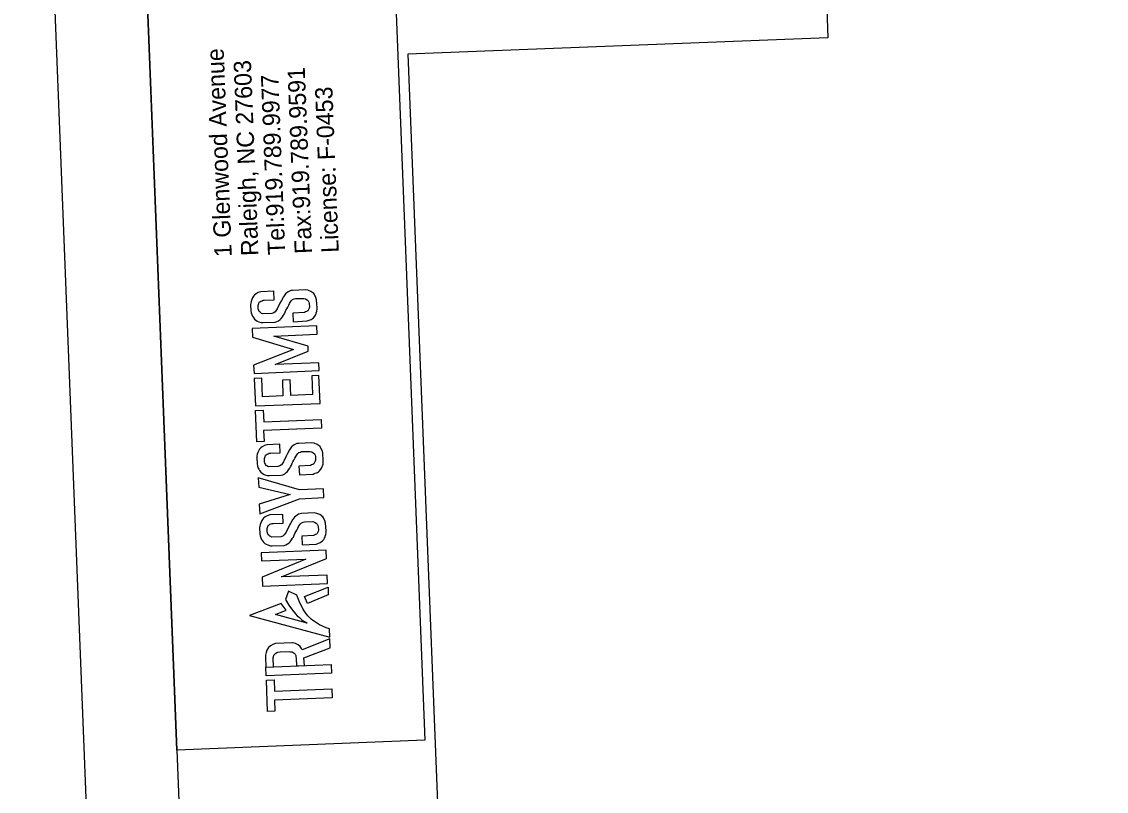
# Model space of a CAD drawing. Extents: x 1627804 to 1628970, y 763730 to 765944.
# Drawn here: x 1627803.6 to 1628095.2, y 765265.9 to 765472.6 of the extents above; entities that cross this region are included whole.
import ezdxf

# ---------------------------------------------------------------- set-up
doc = ezdxf.new("R2010")
doc.units = 0
for name, color, linetype in [('Exist Right of Way Monument Leader', 7, 'Continuous'), ('Exist Right of Way Monument Text', 7, 'Continuous'), ('Exist Roads EOT', 7, 'Continuous'), ('Exist Structure Major Deck Tunnel Box Culvert', 7, 'Continuous'), ('Exist Utilities Gas UG Line', 7, 'Continuous'), ('Scratch_Level_1', 7, 'Continuous')]:
    doc.layers.add(name, color=color, linetype=linetype)

msp = doc.modelspace()

# ---------------------------------------------------------------- linework, layer by layer
at = {"layer": 'Exist Right of Way Monument Leader'}
msp.add_lwpolyline([(1627845.35, 765276.95), (1627837.47, 765476.85), (1627904.11, 765479.48), (1627911.99, 765279.58)], close=True, dxfattribs=at)
at = {"layer": 'Exist Right of Way Monument Text'}
msp.add_lwpolyline([(1627829.58, 765676.74), (1627888.69, 764177.91), (1628937.87, 764219.28), (1628878.77, 765718.12)], close=True, dxfattribs=at)
at = {"layer": 'Exist Roads EOT'}
for points in [[(1627871.45, 765397.9), (1627871.36, 765400.21), (1627867.88, 765400.07), (1627867.19, 765399.84), (1627866.61, 765399.54), (1627866.23, 765399.23), (1627865.89, 765398.84), (1627865.63, 765398.39), (1627865.47, 765397.96), (1627865.47, 765397.96), (1627865.29, 765397.49), (1627865.19, 765397.01), (1627865.12, 765396.68), (1627865.23, 765394.94), (1627865.34, 765394.41), (1627865.44, 765393.96), (1627865.7, 765393.51), (1627865.92, 765393.11), (1627866.22, 765392.73), (1627866.55, 765392.43), (1627866.92, 765392.2), (1627867.32, 765392.02), (1627868.03, 765391.8), (1627868.55, 765391.77), (1627871.71, 765391.89), (1627872.18, 765392.03), (1627872.67, 765392.27), (1627873.07, 765392.58), (1627873.37, 765392.89), (1627873.7, 765393.35), (1627874.03, 765393.82), (1627874.23, 765394.11), (1627874.44, 765394.6), (1627874.65, 765395.09), (1627874.88, 765395.49), (1627875.15, 765395.95), (1627875.4, 765396.48), (1627875.6, 765396.93), (1627875.9, 765397.37), (1627876.18, 765397.69), (1627876.41, 765397.95), (1627876.88, 765398.12), (1627877.18, 765398.23), (1627879.41, 765398.28), (1627879.9, 765398.14), (1627880.33, 765397.91), (1627880.64, 765397.59), (1627880.81, 765397.24), (1627880.9, 765396.91), (1627880.95, 765395.95), (1627880.88, 765395.62), (1627880.7, 765395.28), (1627880.52, 765394.95), (1627880.19, 765394.79), (1627879.86, 765394.64), (1627879.6, 765394.51), (1627876.49, 765394.35), (1627876.61, 765392.02), (1627880.31, 765392.21), (1627880.59, 765392.34), (1627881.44, 765392.64), (1627881.73, 765392.83), (1627882.03, 765393.09), (1627882.39, 765393.49), (1627882.57, 765393.8), (1627882.74, 765394.24), (1627882.8, 765394.4), (1627882.96, 765394.84), (1627883, 765395.38), (1627883.02, 765395.77), (1627882.88, 765397.91), (1627882.72, 765398.5), (1627882.31, 765399.31), (1627882.17, 765399.58), (1627881.36, 765400.17), (1627880.56, 765400.47), (1627879.84, 765400.6), (1627876.43, 765400.41), (1627875.95, 765400.39), (1627875.58, 765400.24), (1627875.24, 765400.03), (1627874.5, 765399.47), (1627873.97, 765398.74), (1627873.43, 765397.74), (1627873.02, 765396.98), (1627872.31, 765395.49), (1627871.78, 765394.71), (1627871.37, 765394.37), (1627871.09, 765394.28), (1627870.81, 765394.19), (1627868.38, 765394.14), (1627868.12, 765394.25), (1627867.86, 765394.37), (1627867.7, 765394.54), (1627867.49, 765394.76), (1627867.38, 765395.02), (1627867.26, 765395.27), (1627867.28, 765395.42), (1627867.21, 765395.43), (1627867.18, 765396.39), (1627867.28, 765396.67), (1627867.38, 765396.95), (1627867.48, 765397.23), (1627867.67, 765397.37), (1627867.94, 765397.57), (1627868.21, 765397.67), (1627868.48, 765397.77), (1627868.79, 765397.78)], [(1627876.67, 765384.57), (1627865.91, 765380.33), (1627866.1, 765378.12), (1627883.55, 765378.9), (1627883.45, 765381), (1627871.78, 765380.48), (1627880.64, 765384.1), (1627880.62, 765385.45), (1627871.37, 765388.16), (1627883.08, 765388.66), (1627882.98, 765390.94), (1627865.58, 765390.19), (1627865.68, 765387.89)], [(1627866.12, 765376.77), (1627866.42, 765369.39), (1627883.83, 765370.09), (1627883.53, 765377.56), (1627881.56, 765377.48), (1627881.76, 765372.44), (1627875.93, 765372.2), (1627875.76, 765376.41), (1627873.68, 765376.33), (1627873.85, 765372.08), (1627868.36, 765371.86), (1627868.16, 765376.87)], [(1627866.8, 765359.71), (1627866.46, 765368.17), (1627868.53, 765368.25), (1627868.66, 765365.15), (1627884.07, 765365.77), (1627884.16, 765363.42), (1627868.65, 765362.79), (1627868.77, 765359.82)], [(1627873.11, 765356.8), (1627873.02, 765359.11), (1627869.54, 765358.97), (1627868.84, 765358.74), (1627868.27, 765358.44), (1627867.89, 765358.13), (1627867.55, 765357.74), (1627867.29, 765357.29), (1627867.13, 765356.86), (1627867.13, 765356.86), (1627866.95, 765356.4), (1627866.85, 765355.91), (1627866.78, 765355.58), (1627866.89, 765353.84), (1627867, 765353.31), (1627867.1, 765352.86), (1627867.35, 765352.41), (1627867.58, 765352.01), (1627867.88, 765351.63), (1627868.21, 765351.33), (1627868.58, 765351.1), (1627868.98, 765350.93), (1627869.69, 765350.7), (1627870.21, 765350.67), (1627873.37, 765350.79), (1627873.84, 765350.93), (1627874.33, 765351.18), (1627874.73, 765351.48), (1627875.03, 765351.79), (1627875.36, 765352.25), (1627875.69, 765352.72), (1627875.89, 765353.01), (1627876.1, 765353.5), (1627876.3, 765354), (1627876.54, 765354.4), (1627876.81, 765354.85), (1627877.06, 765355.39), (1627877.26, 765355.83), (1627877.56, 765356.27), (1627877.84, 765356.59), (1627878.07, 765356.85), (1627878.54, 765357.02), (1627878.84, 765357.13), (1627881.07, 765357.18), (1627881.56, 765357.04), (1627881.99, 765356.81), (1627882.29, 765356.49), (1627882.47, 765356.15), (1627882.56, 765355.81), (1627882.61, 765354.85), (1627882.54, 765354.52), (1627882.36, 765354.19), (1627882.18, 765353.85), (1627881.85, 765353.69), (1627881.52, 765353.54), (1627881.26, 765353.41), (1627878.15, 765353.26), (1627878.27, 765350.92), (1627881.97, 765351.11), (1627882.25, 765351.24), (1627883.1, 765351.54), (1627883.38, 765351.73), (1627883.69, 765352), (1627884.05, 765352.39), (1627884.23, 765352.7), (1627884.4, 765353.14), (1627884.46, 765353.3), (1627884.62, 765353.74), (1627884.65, 765354.28), (1627884.68, 765354.67), (1627884.54, 765356.81), (1627884.38, 765357.4), (1627883.97, 765358.21), (1627883.83, 765358.48), (1627883.02, 765359.07), (1627882.22, 765359.37), (1627881.5, 765359.5), (1627878.08, 765359.31), (1627877.61, 765359.29), (1627877.24, 765359.14), (1627876.9, 765358.94), (1627876.16, 765358.37), (1627875.63, 765357.64), (1627875.09, 765356.64), (1627874.68, 765355.88), (1627873.97, 765354.39), (1627873.44, 765353.61), (1627873.03, 765353.27), (1627872.75, 765353.18), (1627872.47, 765353.09), (1627870.04, 765353.04), (1627869.78, 765353.15), (1627869.52, 765353.27), (1627869.36, 765353.44), (1627869.15, 765353.66), (1627869.03, 765353.92), (1627868.92, 765354.17), (1627868.94, 765354.32), (1627868.87, 765354.33), (1627868.84, 765355.29), (1627868.94, 765355.57), (1627869.04, 765355.85), (1627869.14, 765356.13), (1627869.33, 765356.27), (1627869.6, 765356.47), (1627869.87, 765356.57), (1627870.14, 765356.67), (1627870.45, 765356.68)], [(1627867.49, 765342.97), (1627867.59, 765340.43), (1627878.32, 765344.48), (1627884.86, 765344.77), (1627884.75, 765347.15), (1627878.26, 765346.87), (1627867.16, 765350.09), (1627867.33, 765347.6), (1627875.76, 765345.62)], [(1627873.87, 765337.94), (1627873.78, 765340.25), (1627870.3, 765340.11), (1627869.61, 765339.89), (1627869.03, 765339.58), (1627868.65, 765339.27), (1627868.31, 765338.89), (1627868.05, 765338.44), (1627867.89, 765338), (1627867.89, 765338), (1627867.71, 765337.54), (1627867.61, 765337.05), (1627867.54, 765336.73), (1627867.65, 765334.98), (1627867.76, 765334.46), (1627867.86, 765334), (1627868.12, 765333.55), (1627868.34, 765333.16), (1627868.64, 765332.77), (1627868.97, 765332.48), (1627869.34, 765332.25), (1627869.74, 765332.07), (1627870.45, 765331.84), (1627870.97, 765331.81), (1627874.13, 765331.94), (1627874.61, 765332.07), (1627875.09, 765332.32), (1627875.49, 765332.62), (1627875.79, 765332.93), (1627876.12, 765333.4), (1627876.45, 765333.86), (1627876.65, 765334.16), (1627876.86, 765334.65), (1627877.07, 765335.14), (1627877.3, 765335.54), (1627877.57, 765335.99), (1627877.82, 765336.53), (1627878.02, 765336.97), (1627878.32, 765337.41), (1627878.6, 765337.73), (1627878.83, 765337.99), (1627879.3, 765338.16), (1627879.6, 765338.27), (1627881.83, 765338.32), (1627882.32, 765338.18), (1627882.75, 765337.95), (1627883.06, 765337.64), (1627883.23, 765337.29), (1627883.32, 765336.95), (1627883.37, 765335.99), (1627883.3, 765335.66), (1627883.12, 765335.33), (1627882.94, 765334.99), (1627882.61, 765334.84), (1627882.28, 765334.68), (1627882.02, 765334.56), (1627878.91, 765334.4), (1627879.03, 765332.06), (1627882.73, 765332.25), (1627883.01, 765332.38), (1627883.86, 765332.69), (1627884.15, 765332.87), (1627884.45, 765333.14), (1627884.81, 765333.53), (1627884.99, 765333.84), (1627885.16, 765334.29), (1627885.22, 765334.45), (1627885.38, 765334.88), (1627885.42, 765335.42), (1627885.44, 765335.81), (1627885.3, 765337.95), (1627885.14, 765338.54), (1627884.73, 765339.35), (1627884.59, 765339.62), (1627883.78, 765340.21), (1627882.98, 765340.52), (1627882.26, 765340.64), (1627878.85, 765340.46), (1627878.37, 765340.43), (1627878, 765340.28), (1627877.66, 765340.08), (1627876.92, 765339.51), (1627876.39, 765338.78), (1627875.85, 765337.78), (1627875.44, 765337.02), (1627874.73, 765335.53), (1627874.2, 765334.75), (1627873.79, 765334.41), (1627873.51, 765334.32), (1627873.23, 765334.23), (1627870.8, 765334.18), (1627870.54, 765334.3), (1627870.28, 765334.41), (1627870.12, 765334.58), (1627869.91, 765334.81), (1627869.8, 765335.06), (1627869.68, 765335.31), (1627869.7, 765335.46), (1627869.63, 765335.48), (1627869.6, 765336.43), (1627869.7, 765336.72), (1627869.8, 765337), (1627869.9, 765337.28), (1627870.09, 765337.41), (1627870.36, 765337.61), (1627870.63, 765337.71), (1627870.9, 765337.82), (1627871.21, 765337.82)], [(1627868.36, 765321.01), (1627885.81, 765321.72), (1627885.72, 765323.95), (1627873.45, 765323.46), (1627885.57, 765328.39), (1627885.45, 765330.64), (1627867.96, 765329.93), (1627868.05, 765327.75), (1627880.02, 765328.24), (1627868.26, 765323.37)], [(1627864.85, 765313.1), (1627886.44, 765307.28), (1627886.34, 765309.5), (1627885.48, 765309.81), (1627884.3, 765310.34), (1627883.66, 765310.62), (1627883.11, 765310.98), (1627882.33, 765311.47), (1627881.85, 765311.78), (1627881.44, 765312.14), (1627881.04, 765312.51), (1627880.52, 765312.98), (1627880.23, 765313.37), (1627879.89, 765313.78), (1627879.54, 765314.32), (1627879.24, 765314.8), (1627878.63, 765316), (1627878.18, 765316.98), (1627877.55, 765318.6), (1627875.37, 765319.65), (1627874.5, 765317.44), (1627875.45, 765315.84), (1627876.41, 765314.5), (1627877.24, 765313.55), (1627877.69, 765313.04), (1627878.28, 765312.53), (1627878.86, 765312.02), (1627879.3, 765311.64), (1627879.97, 765311.29), (1627880.33, 765311.09), (1627871.86, 765313.39), (1627874.71, 765314.5), (1627873.38, 765316.35)], [(1627880.44, 765316.33), (1627879.61, 765318.22), (1627885.95, 765320.73), (1627885.95, 765318.63)], [(1627871.34, 765299.32), (1627871.24, 765301.71), (1627871.28, 765302.01), (1627871.43, 765302.42), (1627871.63, 765302.75), (1627871.9, 765302.99), (1627872.22, 765303.16), (1627872.47, 765303.29), (1627873.05, 765303.32), (1627875.54, 765303.43), (1627875.87, 765303.38), (1627876.32, 765303.31), (1627876.62, 765303.19), (1627876.89, 765303), (1627877.11, 765302.74), (1627877.28, 765302.32), (1627877.33, 765302), (1627877.39, 765301.67), (1627877.48, 765299.57), (1627879.59, 765299.66), (1627879.49, 765301.77), (1627886.56, 765304.42), (1627886.44, 765306.83), (1627879.01, 765303.89), (1627878.86, 765304.26), (1627878.44, 765304.78), (1627877.89, 765305.25), (1627877.24, 765305.57), (1627876.6, 765305.76), (1627876.41, 765305.74), (1627871.85, 765305.6), (1627871.11, 765305.36), (1627870.45, 765304.98), (1627869.99, 765304.55), (1627869.55, 765303.83), (1627869.35, 765303.14), (1627869.15, 765302.46), (1627869.17, 765302.05), (1627869.26, 765299.24)], [(1627869.35, 765296.92), (1627869.26, 765299.24), (1627886.81, 765299.95), (1627886.9, 765297.63)], [(1627869.72, 765287.31), (1627869.38, 765295.77), (1627871.45, 765295.85), (1627871.58, 765292.75), (1627886.99, 765293.37), (1627887.08, 765291.02), (1627871.57, 765290.39), (1627871.69, 765287.42)]]:
    msp.add_lwpolyline(points, close=True, dxfattribs=at)
at = {"layer": 'Exist Structure Major Deck Tunnel Box Culvert'}
msp.add_lwpolyline([(1628282.65, 764219.07), (1628522.47, 764228.52), (1628936.86, 764244.86), (1628878.77, 765718.12), (1628011.82, 765683.93), (1628019.82, 765481.21), (1628020.32, 765468.29), (1627907.44, 765463.84), (1627915.37, 765262.78), (1627849.84, 765260.19), (1627891.5, 764203.89)], close=True, dxfattribs=at)
at = {"layer": 'Exist Utilities Gas UG Line'}
msp.add_lwpolyline([(1628969.75, 764045.4), (1628902.76, 765744.08), (1627803.62, 765700.74), (1627870.6, 764002.06)], close=True, dxfattribs=at)

# ---------------------------------------------------------------- texts
at = {"layer": 'Scratch_Level_1'}
for s, p in [('1 Glenwood Avenue', (1627860.1, 765409.49)), ('Raleigh, NC 27603', (1627867.29, 765409.77)), ('Fax:919.789.9591', (1627881.67, 765410.34)), ('Tel:919.789.9977 ', (1627874.48, 765410.05)), ('License: F-0453', (1627888.86, 765410.62))]:
    msp.add_text(s, height=4.6576, rotation=92.2582, dxfattribs=at).set_placement(p)

doc.saveas('drawing.dxf')
